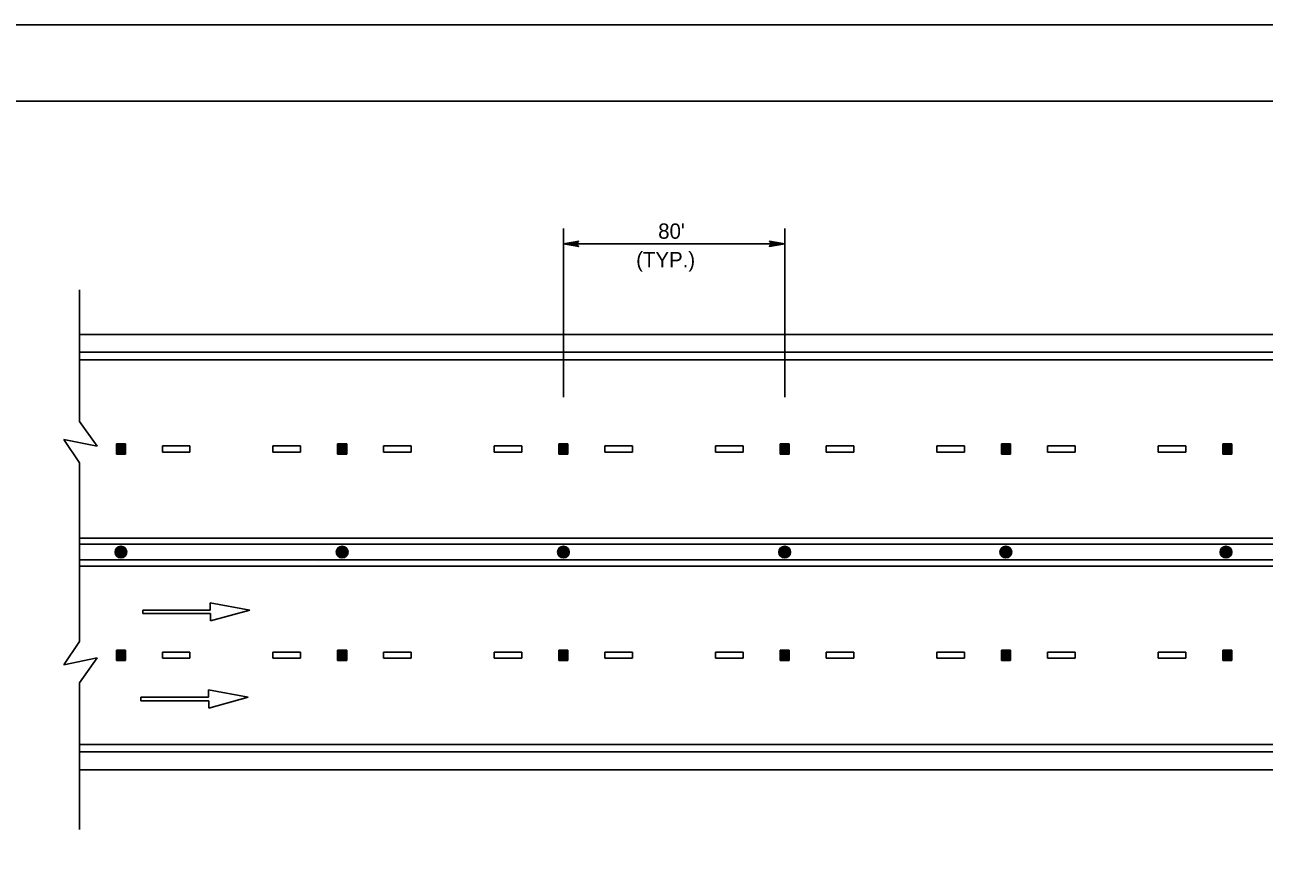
# Model space of a CAD drawing. Extents: x 639362 to 641108, y 298458 to 299646.
# Drawn here: x 640558.2 to 640801.8, y 299484.5 to 299645.6 of the extents above; entities that cross this region are included whole.
import ezdxf

# ---------------------------------------------------------------- set-up
doc = ezdxf.new("R2010")
doc.units = 0
for name, color, linetype in [('1', 7, 'Continuous'), ('2', 7, 'Continuous'), ('3', 7, 'Continuous'), ('PLT-BNDY', 7, 'Continuous')]:
    doc.layers.add(name, color=color, linetype=linetype)

# ---------------------------------------------------------------- blocks, each defined once
blk = doc.blocks.new('RARROW')
at = {"layer": '3'}
blk.add_lwpolyline([(-2.2695, 0.285), (-2.184875, 0.12075), (0, 0), (-2.2695, 0.285), (-2.38575, 0.384625), (0, 0), (-2.183125, -0.108), (-2.262875, -0.2705), (0, 0), (-2.38575, -0.379125), (-2.262875, -0.2705)], dxfattribs=at)

msp = doc.modelspace()

# ---------------------------------------------------------------- linework, layer by layer
at = {"layer": '1'}
msp.add_line((640243.31, 299630.63), (641029.31, 299630.63), dxfattribs=at)
at = {"layer": '2'}
for p, q in [((640664.07, 299572.37), (640664.07, 299605.55)), ((640707.56, 299572.37), (640707.56, 299605.55)), ((640707.56, 299602.55), (640664.07, 299602.55)), ((640568.94, 299593.51), (640568.94, 299567.63)), ((640568.94, 299584.74), (640846.38, 299584.74)), ((640568.94, 299581.24), (640846.38, 299581.24)), ((640568.94, 299579.74), (640846.38, 299579.74)), ((640572.43, 299562.73), (640568.94, 299567.63)), ((640568.94, 299559.5), (640565.89, 299564.08)), ((640565.89, 299564.08), (640572.43, 299562.73)), ((640576.2, 299563.23), (640577.97, 299563.23)), ((640576.2, 299561.19), (640576.2, 299563.23)), ((640577.97, 299561.19), (640576.2, 299561.19)), ((640576.37, 299563.05), (640577.79, 299563.05)), ((640576.37, 299561.36), (640576.37, 299563.05)), ((640577.79, 299561.36), (640576.37, 299561.36)), ((640576.55, 299562.87), (640577.62, 299562.87)), ((640576.55, 299561.54), (640576.55, 299562.87)), ((640577.62, 299561.54), (640576.55, 299561.54)), ((640576.73, 299561.72), (640576.73, 299562.69)), ((640576.73, 299562.69), (640577.44, 299562.69)), ((640577.44, 299561.72), (640576.73, 299561.72)), ((640576.91, 299562.52), (640577.26, 299562.52)), ((640576.91, 299561.9), (640576.91, 299562.52)), ((640577.26, 299561.9), (640576.91, 299561.9)), ((640577.08, 299562.34), (640577.08, 299562.07)), ((640577.26, 299562.52), (640577.26, 299561.9)), ((640577.44, 299562.69), (640577.44, 299561.72)), ((640577.62, 299562.87), (640577.62, 299561.54)), ((640577.79, 299563.05), (640577.79, 299561.36)), ((640577.97, 299563.23), (640577.97, 299561.19)), ((640585.24, 299562.81), (640590.67, 299562.81)), ((640585.24, 299561.61), (640585.24, 299562.81)), ((640590.67, 299561.61), (640585.24, 299561.61)), ((640590.67, 299562.81), (640590.67, 299561.61)), ((640612.42, 299562.81), (640606.98, 299562.81)), ((640606.98, 299562.81), (640606.98, 299561.61)), ((640606.98, 299561.61), (640612.42, 299561.61)), ((640612.42, 299561.61), (640612.42, 299562.81)), ((640619.69, 299563.23), (640621.47, 299563.23)), ((640619.69, 299561.19), (640619.69, 299563.23)), ((640621.47, 299561.19), (640619.69, 299561.19)), ((640619.87, 299563.05), (640621.29, 299563.05)), ((640619.87, 299561.36), (640619.87, 299563.05)), ((640621.29, 299561.36), (640619.87, 299561.36)), ((640620.05, 299562.87), (640621.11, 299562.87)), ((640620.05, 299561.54), (640620.05, 299562.87)), ((640621.11, 299561.54), (640620.05, 299561.54)), ((640620.22, 299561.72), (640620.22, 299562.69)), ((640620.22, 299562.69), (640620.93, 299562.69)), ((640620.93, 299561.72), (640620.22, 299561.72)), ((640620.4, 299562.52), (640620.76, 299562.52)), ((640620.4, 299561.9), (640620.4, 299562.52)), ((640620.76, 299561.9), (640620.4, 299561.9)), ((640620.58, 299562.34), (640620.58, 299562.07)), ((640620.76, 299562.52), (640620.76, 299561.9)), ((640620.93, 299562.69), (640620.93, 299561.72)), ((640621.11, 299562.87), (640621.11, 299561.54)), ((640621.29, 299563.05), (640621.29, 299561.36)), ((640621.47, 299563.23), (640621.47, 299561.19)), ((640628.73, 299562.81), (640634.17, 299562.81)), ((640628.73, 299561.61), (640628.73, 299562.81)), ((640634.17, 299561.61), (640628.73, 299561.61)), ((640634.17, 299562.81), (640634.17, 299561.61)), ((640655.91, 299562.81), (640650.48, 299562.81)), ((640650.48, 299562.81), (640650.48, 299561.61)), ((640650.48, 299561.61), (640655.91, 299561.61)), ((640655.91, 299561.61), (640655.91, 299562.81)), ((640663.18, 299563.23), (640664.96, 299563.23)), ((640663.18, 299561.19), (640663.18, 299563.23)), ((640664.96, 299561.19), (640663.18, 299561.19)), ((640663.36, 299563.05), (640664.78, 299563.05)), ((640663.36, 299561.36), (640663.36, 299563.05)), ((640664.78, 299561.36), (640663.36, 299561.36)), ((640663.54, 299562.87), (640664.6, 299562.87)), ((640663.54, 299561.54), (640663.54, 299562.87)), ((640664.6, 299561.54), (640663.54, 299561.54)), ((640663.72, 299561.72), (640663.72, 299562.69)), ((640663.72, 299562.69), (640664.43, 299562.69)), ((640664.43, 299561.72), (640663.72, 299561.72)), ((640663.89, 299562.52), (640664.25, 299562.52)), ((640663.89, 299561.9), (640663.89, 299562.52)), ((640664.25, 299561.9), (640663.89, 299561.9)), ((640664.07, 299562.34), (640664.07, 299562.07)), ((640664.25, 299562.52), (640664.25, 299561.9)), ((640664.43, 299562.69), (640664.43, 299561.72)), ((640664.6, 299562.87), (640664.6, 299561.54)), ((640664.78, 299563.05), (640664.78, 299561.36)), ((640664.96, 299563.23), (640664.96, 299561.19)), ((640677.66, 299562.81), (640672.22, 299562.81)), ((640672.22, 299562.81), (640672.22, 299561.61)), ((640672.22, 299561.61), (640677.66, 299561.61)), ((640677.66, 299561.61), (640677.66, 299562.81)), ((640699.41, 299562.81), (640693.97, 299562.81)), ((640693.97, 299562.81), (640693.97, 299561.61)), ((640693.97, 299561.61), (640699.41, 299561.61)), ((640699.41, 299561.61), (640699.41, 299562.81)), ((640706.68, 299563.23), (640708.45, 299563.23)), ((640706.68, 299561.19), (640706.68, 299563.23)), ((640708.45, 299561.19), (640706.68, 299561.19)), ((640706.85, 299563.05), (640708.27, 299563.05)), ((640706.85, 299561.36), (640706.85, 299563.05)), ((640708.27, 299561.36), (640706.85, 299561.36)), ((640707.03, 299562.87), (640708.1, 299562.87)), ((640707.03, 299561.54), (640707.03, 299562.87)), ((640708.1, 299561.54), (640707.03, 299561.54)), ((640707.21, 299561.72), (640707.21, 299562.69)), ((640707.21, 299562.69), (640707.92, 299562.69)), ((640707.92, 299561.72), (640707.21, 299561.72)), ((640707.39, 299562.52), (640707.74, 299562.52)), ((640707.39, 299561.9), (640707.39, 299562.52)), ((640707.74, 299561.9), (640707.39, 299561.9)), ((640707.56, 299562.34), (640707.56, 299562.07)), ((640707.74, 299562.52), (640707.74, 299561.9)), ((640707.92, 299562.69), (640707.92, 299561.72)), ((640708.1, 299562.87), (640708.1, 299561.54)), ((640708.27, 299563.05), (640708.27, 299561.36)), ((640708.45, 299563.23), (640708.45, 299561.19)), ((640721.15, 299562.81), (640715.72, 299562.81)), ((640715.72, 299562.81), (640715.72, 299561.61)), ((640715.72, 299561.61), (640721.15, 299561.61)), ((640721.15, 299561.61), (640721.15, 299562.81)), ((640742.9, 299562.81), (640737.46, 299562.81)), ((640737.46, 299562.81), (640737.46, 299561.61)), ((640737.46, 299561.61), (640742.9, 299561.61)), ((640742.9, 299561.61), (640742.9, 299562.81)), ((640750.17, 299563.23), (640751.95, 299563.23)), ((640750.17, 299561.19), (640750.17, 299563.23)), ((640751.95, 299561.19), (640750.17, 299561.19)), ((640750.35, 299563.05), (640751.77, 299563.05)), ((640750.35, 299561.36), (640750.35, 299563.05)), ((640751.77, 299561.36), (640750.35, 299561.36)), ((640750.53, 299562.87), (640751.59, 299562.87)), ((640750.53, 299561.54), (640750.53, 299562.87)), ((640751.59, 299561.54), (640750.53, 299561.54)), ((640750.7, 299561.72), (640750.7, 299562.69)), ((640750.7, 299562.69), (640751.41, 299562.69)), ((640751.41, 299561.72), (640750.7, 299561.72)), ((640750.88, 299562.52), (640751.23, 299562.52)), ((640750.88, 299561.9), (640750.88, 299562.52)), ((640751.23, 299561.9), (640750.88, 299561.9)), ((640751.06, 299562.34), (640751.06, 299562.07)), ((640751.23, 299562.52), (640751.23, 299561.9)), ((640751.41, 299562.69), (640751.41, 299561.72)), ((640751.59, 299562.87), (640751.59, 299561.54)), ((640751.77, 299563.05), (640751.77, 299561.36)), ((640751.95, 299563.23), (640751.95, 299561.19)), ((640764.65, 299562.81), (640759.21, 299562.81)), ((640759.21, 299562.81), (640759.21, 299561.61)), ((640759.21, 299561.61), (640764.65, 299561.61)), ((640764.65, 299561.61), (640764.65, 299562.81)), ((640780.96, 299562.81), (640786.39, 299562.81)), ((640780.96, 299561.61), (640780.96, 299562.81)), ((640786.39, 299561.61), (640780.96, 299561.61)), ((640786.39, 299562.81), (640786.39, 299561.61)), ((640793.66, 299563.23), (640795.44, 299563.23)), ((640793.66, 299561.19), (640793.66, 299563.23)), ((640795.44, 299561.19), (640793.66, 299561.19)), ((640793.84, 299563.05), (640795.26, 299563.05)), ((640793.84, 299561.36), (640793.84, 299563.05)), ((640795.26, 299561.36), (640793.84, 299561.36)), ((640794.02, 299562.87), (640795.08, 299562.87)), ((640794.02, 299561.54), (640794.02, 299562.87)), ((640795.08, 299561.54), (640794.02, 299561.54)), ((640794.2, 299561.72), (640794.2, 299562.69)), ((640794.2, 299562.69), (640794.91, 299562.69)), ((640794.91, 299561.72), (640794.2, 299561.72)), ((640794.37, 299562.52), (640794.73, 299562.52)), ((640794.37, 299561.9), (640794.37, 299562.52)), ((640794.73, 299561.9), (640794.37, 299561.9)), ((640794.55, 299562.34), (640794.55, 299562.07)), ((640794.73, 299562.52), (640794.73, 299561.9)), ((640794.91, 299562.69), (640794.91, 299561.72)), ((640795.08, 299562.87), (640795.08, 299561.54)), ((640795.26, 299563.05), (640795.26, 299561.36)), ((640795.44, 299563.23), (640795.44, 299561.19)), ((640568.94, 299559.5), (640568.94, 299524.36)), ((640846.38, 299544.68), (640568.94, 299544.68)), ((640568.94, 299544.68), (640568.94, 299543.48)), ((640568.94, 299543.48), (640846.38, 299543.48)), ((640846.38, 299540.38), (640568.94, 299540.38)), ((640568.94, 299540.38), (640568.94, 299539.18)), ((640568.94, 299539.18), (640846.38, 299539.18)), ((640615.94, 299540.06), (640615.94, 299540.06)), ((640615.94, 299540.06), (640615.94, 299540.06)), ((640602.45, 299530.5), (640594.65, 299531.98)), ((640594.65, 299531.98), (640594.65, 299530.53)), ((640594.65, 299530.53), (640581.4, 299530.53)), ((640581.4, 299530.53), (640581.4, 299529.83)), ((640581.4, 299529.83), (640594.73, 299529.83)), ((640594.73, 299528.38), (640602.45, 299530.5)), ((640594.73, 299529.83), (640594.73, 299528.38)), ((640568.94, 299524.36), (640565.89, 299519.78)), ((640576.2, 299522.67), (640577.97, 299522.67)), ((640576.2, 299520.63), (640576.2, 299522.67)), ((640576.37, 299522.49), (640577.79, 299522.49)), ((640576.37, 299520.81), (640576.37, 299522.49)), ((640576.55, 299522.31), (640577.62, 299522.31)), ((640576.55, 299520.98), (640576.55, 299522.31)), ((640576.73, 299521.16), (640576.73, 299522.14)), ((640576.73, 299522.14), (640577.44, 299522.14)), ((640576.91, 299521.96), (640577.26, 299521.96)), ((640576.91, 299521.34), (640576.91, 299521.96)), ((640577.26, 299521.96), (640577.26, 299521.34)), ((640577.44, 299522.14), (640577.44, 299521.16)), ((640577.62, 299522.31), (640577.62, 299520.98)), ((640577.79, 299522.49), (640577.79, 299520.81)), ((640577.97, 299522.67), (640577.97, 299520.63)), ((640585.24, 299522.25), (640590.67, 299522.25)), ((640585.24, 299521.05), (640585.24, 299522.25)), ((640590.67, 299522.25), (640590.67, 299521.05)), ((640612.42, 299522.25), (640606.98, 299522.25)), ((640606.98, 299522.25), (640606.98, 299521.05)), ((640612.42, 299521.05), (640612.42, 299522.25)), ((640619.69, 299522.67), (640621.47, 299522.67)), ((640619.69, 299520.63), (640619.69, 299522.67)), ((640619.87, 299522.49), (640621.29, 299522.49)), ((640619.87, 299520.81), (640619.87, 299522.49)), ((640620.05, 299522.31), (640621.11, 299522.31)), ((640620.05, 299520.98), (640620.05, 299522.31)), ((640620.22, 299521.16), (640620.22, 299522.14)), ((640620.22, 299522.14), (640620.93, 299522.14)), ((640620.4, 299521.96), (640620.76, 299521.96)), ((640620.4, 299521.34), (640620.4, 299521.96)), ((640620.76, 299521.96), (640620.76, 299521.34)), ((640620.93, 299522.14), (640620.93, 299521.16)), ((640621.11, 299522.31), (640621.11, 299520.98)), ((640621.29, 299522.49), (640621.29, 299520.81)), ((640621.47, 299522.67), (640621.47, 299520.63)), ((640628.73, 299522.25), (640634.17, 299522.25)), ((640628.73, 299521.05), (640628.73, 299522.25)), ((640634.17, 299522.25), (640634.17, 299521.05)), ((640655.91, 299522.25), (640650.48, 299522.25)), ((640650.48, 299522.25), (640650.48, 299521.05)), ((640655.91, 299521.05), (640655.91, 299522.25)), ((640663.18, 299522.67), (640664.96, 299522.67)), ((640663.18, 299520.63), (640663.18, 299522.67)), ((640663.36, 299522.49), (640664.78, 299522.49)), ((640663.36, 299520.81), (640663.36, 299522.49)), ((640663.54, 299522.31), (640664.6, 299522.31)), ((640663.54, 299520.98), (640663.54, 299522.31)), ((640663.72, 299521.16), (640663.72, 299522.14)), ((640663.72, 299522.14), (640664.43, 299522.14)), ((640663.89, 299521.96), (640664.25, 299521.96)), ((640663.89, 299521.34), (640663.89, 299521.96)), ((640664.25, 299521.96), (640664.25, 299521.34)), ((640664.43, 299522.14), (640664.43, 299521.16)), ((640664.6, 299522.31), (640664.6, 299520.98)), ((640664.78, 299522.49), (640664.78, 299520.81)), ((640664.96, 299522.67), (640664.96, 299520.63)), ((640677.66, 299522.25), (640672.22, 299522.25)), ((640672.22, 299522.25), (640672.22, 299521.05)), ((640677.66, 299521.05), (640677.66, 299522.25)), ((640699.41, 299522.25), (640693.97, 299522.25)), ((640693.97, 299522.25), (640693.97, 299521.05)), ((640699.41, 299521.05), (640699.41, 299522.25)), ((640706.68, 299522.67), (640708.45, 299522.67)), ((640706.68, 299520.63), (640706.68, 299522.67)), ((640706.85, 299522.49), (640708.27, 299522.49)), ((640706.85, 299520.81), (640706.85, 299522.49)), ((640707.03, 299522.31), (640708.1, 299522.31)), ((640707.03, 299520.98), (640707.03, 299522.31)), ((640707.21, 299521.16), (640707.21, 299522.14)), ((640707.21, 299522.14), (640707.92, 299522.14)), ((640707.39, 299521.96), (640707.74, 299521.96)), ((640707.39, 299521.34), (640707.39, 299521.96)), ((640707.74, 299521.96), (640707.74, 299521.34)), ((640707.92, 299522.14), (640707.92, 299521.16)), ((640708.1, 299522.31), (640708.1, 299520.98)), ((640708.27, 299522.49), (640708.27, 299520.81)), ((640708.45, 299522.67), (640708.45, 299520.63)), ((640721.15, 299522.25), (640715.72, 299522.25)), ((640715.72, 299522.25), (640715.72, 299521.05)), ((640721.15, 299521.05), (640721.15, 299522.25)), ((640742.9, 299522.25), (640737.46, 299522.25)), ((640737.46, 299522.25), (640737.46, 299521.05)), ((640742.9, 299521.05), (640742.9, 299522.25)), ((640750.17, 299522.67), (640751.95, 299522.67)), ((640750.17, 299520.63), (640750.17, 299522.67)), ((640750.35, 299522.49), (640751.77, 299522.49)), ((640750.35, 299520.81), (640750.35, 299522.49)), ((640750.53, 299522.31), (640751.59, 299522.31)), ((640750.53, 299520.98), (640750.53, 299522.31)), ((640750.7, 299521.16), (640750.7, 299522.14)), ((640750.7, 299522.14), (640751.41, 299522.14)), ((640750.88, 299521.96), (640751.23, 299521.96)), ((640750.88, 299521.34), (640750.88, 299521.96)), ((640751.23, 299521.96), (640751.23, 299521.34)), ((640751.41, 299522.14), (640751.41, 299521.16)), ((640751.59, 299522.31), (640751.59, 299520.98)), ((640751.77, 299522.49), (640751.77, 299520.81)), ((640751.95, 299522.67), (640751.95, 299520.63)), ((640764.65, 299522.25), (640759.21, 299522.25)), ((640759.21, 299522.25), (640759.21, 299521.05)), ((640764.65, 299521.05), (640764.65, 299522.25)), ((640780.96, 299522.25), (640786.39, 299522.25)), ((640780.96, 299521.05), (640780.96, 299522.25)), ((640786.39, 299522.25), (640786.39, 299521.05)), ((640793.66, 299522.67), (640795.44, 299522.67)), ((640793.66, 299520.63), (640793.66, 299522.67)), ((640793.84, 299522.49), (640795.26, 299522.49)), ((640793.84, 299520.81), (640793.84, 299522.49)), ((640794.02, 299522.31), (640795.08, 299522.31)), ((640794.02, 299520.98), (640794.02, 299522.31)), ((640794.2, 299521.16), (640794.2, 299522.14)), ((640794.2, 299522.14), (640794.91, 299522.14)), ((640794.37, 299521.96), (640794.73, 299521.96)), ((640794.37, 299521.34), (640794.37, 299521.96)), ((640794.73, 299521.96), (640794.73, 299521.34)), ((640794.91, 299522.14), (640794.91, 299521.16)), ((640795.08, 299522.31), (640795.08, 299520.98)), ((640795.26, 299522.49), (640795.26, 299520.81)), ((640795.44, 299522.67), (640795.44, 299520.63)), ((640565.89, 299519.78), (640572.43, 299521.13)), ((640572.43, 299521.13), (640568.94, 299516.24)), ((640577.97, 299520.63), (640576.2, 299520.63)), ((640577.79, 299520.81), (640576.37, 299520.81)), ((640577.62, 299520.98), (640576.55, 299520.98)), ((640577.44, 299521.16), (640576.73, 299521.16)), ((640577.26, 299521.34), (640576.91, 299521.34)), ((640577.08, 299521.78), (640577.08, 299521.51)), ((640590.67, 299521.05), (640585.24, 299521.05)), ((640606.98, 299521.05), (640612.42, 299521.05)), ((640621.47, 299520.63), (640619.69, 299520.63)), ((640621.29, 299520.81), (640619.87, 299520.81)), ((640621.11, 299520.98), (640620.05, 299520.98)), ((640620.93, 299521.16), (640620.22, 299521.16)), ((640620.76, 299521.34), (640620.4, 299521.34)), ((640620.58, 299521.78), (640620.58, 299521.51)), ((640634.17, 299521.05), (640628.73, 299521.05)), ((640650.48, 299521.05), (640655.91, 299521.05)), ((640664.96, 299520.63), (640663.18, 299520.63)), ((640664.78, 299520.81), (640663.36, 299520.81)), ((640664.6, 299520.98), (640663.54, 299520.98)), ((640664.43, 299521.16), (640663.72, 299521.16)), ((640664.25, 299521.34), (640663.89, 299521.34)), ((640664.07, 299521.78), (640664.07, 299521.51)), ((640672.22, 299521.05), (640677.66, 299521.05)), ((640693.97, 299521.05), (640699.41, 299521.05)), ((640708.45, 299520.63), (640706.68, 299520.63)), ((640708.27, 299520.81), (640706.85, 299520.81)), ((640708.1, 299520.98), (640707.03, 299520.98)), ((640707.92, 299521.16), (640707.21, 299521.16)), ((640707.74, 299521.34), (640707.39, 299521.34)), ((640707.56, 299521.78), (640707.56, 299521.51)), ((640715.72, 299521.05), (640721.15, 299521.05)), ((640737.46, 299521.05), (640742.9, 299521.05)), ((640751.95, 299520.63), (640750.17, 299520.63)), ((640751.77, 299520.81), (640750.35, 299520.81)), ((640751.59, 299520.98), (640750.53, 299520.98)), ((640751.41, 299521.16), (640750.7, 299521.16)), ((640751.23, 299521.34), (640750.88, 299521.34)), ((640751.06, 299521.78), (640751.06, 299521.51)), ((640759.21, 299521.05), (640764.65, 299521.05)), ((640786.39, 299521.05), (640780.96, 299521.05)), ((640795.44, 299520.63), (640793.66, 299520.63)), ((640795.26, 299520.81), (640793.84, 299520.81)), ((640795.08, 299520.98), (640794.02, 299520.98)), ((640794.91, 299521.16), (640794.2, 299521.16)), ((640794.73, 299521.34), (640794.37, 299521.34)), ((640794.55, 299521.78), (640794.55, 299521.51)), ((640568.94, 299516.24), (640568.94, 299487.39)), ((640602.08, 299513.37), (640594.28, 299514.84)), ((640594.28, 299514.84), (640594.28, 299513.4)), ((640594.28, 299513.4), (640581.03, 299513.4)), ((640581.03, 299513.4), (640581.03, 299512.69)), ((640581.03, 299512.69), (640594.36, 299512.69)), ((640594.36, 299511.25), (640602.08, 299513.37)), ((640594.36, 299512.69), (640594.36, 299511.25)), ((640568.94, 299504.12), (640846.38, 299504.12)), ((640568.94, 299502.62), (640846.38, 299502.62)), ((640568.94, 299499.12), (640846.38, 299499.12))]:
    msp.add_line(p, q, dxfattribs=at)
for centre, radius in [((640577.09, 299541.93), 1.15), ((640577.09, 299541.93), 1.07), ((640577.09, 299541.93), 0.985), ((640577.09, 299541.93), 0.904), ((640577.09, 299541.93), 0.822), ((640577.09, 299541.93), 0.741), ((640577.09, 299541.93), 0.659), ((640577.09, 299541.93), 0.578), ((640577.09, 299541.93), 0.496), ((640577.09, 299541.93), 0.414), ((640577.09, 299541.93), 0.333), ((640577.09, 299541.93), 0.251), ((640577.09, 299541.93), 0.17), ((640577.09, 299541.93), 0.0881), ((640620.58, 299541.93), 1.15), ((640620.58, 299541.93), 1.07), ((640620.58, 299541.93), 0.985), ((640620.58, 299541.93), 0.904), ((640620.58, 299541.93), 0.822), ((640620.58, 299541.93), 0.741), ((640620.58, 299541.93), 0.659), ((640620.58, 299541.93), 0.578), ((640620.58, 299541.93), 0.496), ((640620.58, 299541.93), 0.414), ((640620.58, 299541.93), 0.333), ((640620.58, 299541.93), 0.251), ((640620.58, 299541.93), 0.17), ((640620.58, 299541.93), 0.0881), ((640664.07, 299541.93), 1.15), ((640664.07, 299541.93), 1.07), ((640664.07, 299541.93), 0.985), ((640664.07, 299541.93), 0.904), ((640664.07, 299541.93), 0.822), ((640664.07, 299541.93), 0.741), ((640664.07, 299541.93), 0.659), ((640664.07, 299541.93), 0.578), ((640664.07, 299541.93), 0.496), ((640664.07, 299541.93), 0.414), ((640664.07, 299541.93), 0.333), ((640664.07, 299541.93), 0.251), ((640664.07, 299541.93), 0.17), ((640664.07, 299541.93), 0.0881), ((640707.56, 299541.93), 1.15), ((640707.56, 299541.93), 1.07), ((640707.56, 299541.93), 0.985), ((640707.56, 299541.93), 0.904), ((640707.56, 299541.93), 0.822), ((640707.56, 299541.93), 0.741), ((640707.56, 299541.93), 0.659), ((640707.56, 299541.93), 0.578), ((640707.56, 299541.93), 0.496), ((640707.56, 299541.93), 0.414), ((640707.56, 299541.93), 0.333), ((640707.56, 299541.93), 0.251), ((640707.56, 299541.93), 0.17), ((640707.56, 299541.93), 0.0881), ((640751.03, 299541.93), 1.15), ((640751.03, 299541.93), 1.07), ((640751.03, 299541.93), 0.985), ((640751.03, 299541.93), 0.904), ((640751.03, 299541.93), 0.822), ((640751.03, 299541.93), 0.741), ((640751.03, 299541.93), 0.659), ((640751.03, 299541.93), 0.578), ((640751.03, 299541.93), 0.496), ((640751.03, 299541.93), 0.414), ((640751.03, 299541.93), 0.333), ((640751.03, 299541.93), 0.251), ((640751.03, 299541.93), 0.17), ((640751.03, 299541.93), 0.0881), ((640794.3, 299541.93), 1.15), ((640794.3, 299541.93), 1.07), ((640794.3, 299541.93), 0.985), ((640794.3, 299541.93), 0.904), ((640794.3, 299541.93), 0.822), ((640794.3, 299541.93), 0.741), ((640794.3, 299541.93), 0.659), ((640794.3, 299541.93), 0.578), ((640794.3, 299541.93), 0.496), ((640794.3, 299541.93), 0.414), ((640794.3, 299541.93), 0.333), ((640794.3, 299541.93), 0.251), ((640794.3, 299541.93), 0.17), ((640794.3, 299541.93), 0.0881)]:
    msp.add_circle(centre, radius, dxfattribs=at)
at = {"layer": 'PLT-BNDY'}
msp.add_lwpolyline([(640203.31, 299645.63), (641044.31, 299645.63), (641044.31, 299051.63), (640203.31, 299051.63)], close=True, dxfattribs=at)

# ---------------------------------------------------------------- block references
at = {"layer": '2', "xscale": 1.2574347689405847, "yscale": 1.3092961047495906, "rotation": 180}
msp.add_blockref('RARROW', (640664.07, 299602.55), dxfattribs=at)
at = {"layer": '2', "xscale": 1.2574347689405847, "yscale": 1.3092961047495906}
msp.add_blockref('RARROW', (640707.56, 299602.55), dxfattribs=at)

# ---------------------------------------------------------------- texts
at = {"layer": '2'}
for s, p in [("80'", (640682.7, 299603.55)), ('(TYP.)', (640678.37, 299597.95))]:
    msp.add_text(s, height=3, dxfattribs=at).set_placement(p)

doc.saveas('drawing.dxf')
